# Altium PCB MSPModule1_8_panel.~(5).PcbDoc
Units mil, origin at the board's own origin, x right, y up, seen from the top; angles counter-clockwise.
Board outline 5760 x 6000 mil, 2 copper layers (Top Layer, Bottom Layer); 0 components, 0 nets, 0 pads, 0 vias.
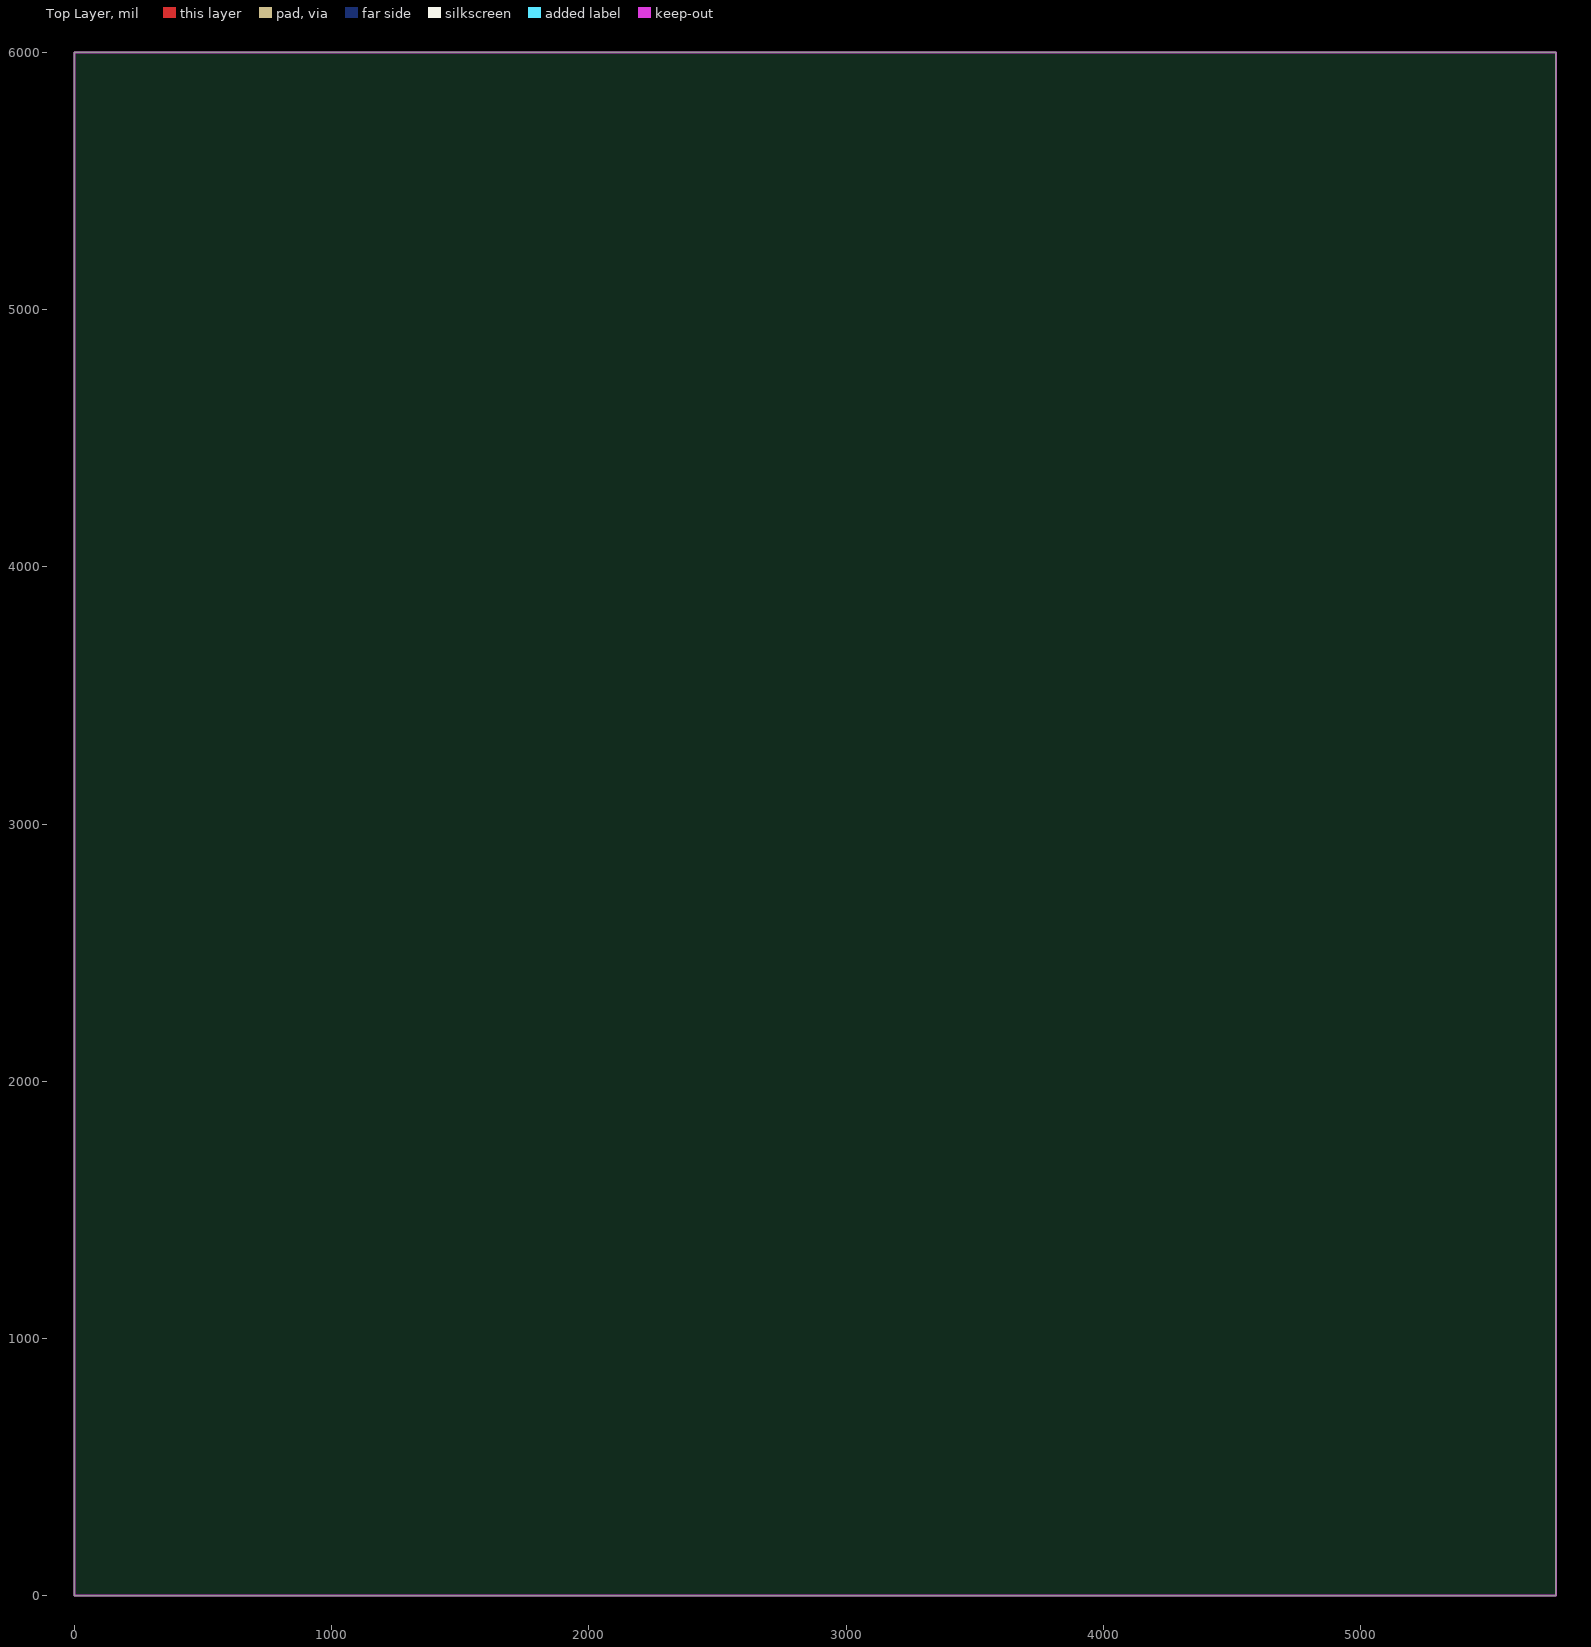
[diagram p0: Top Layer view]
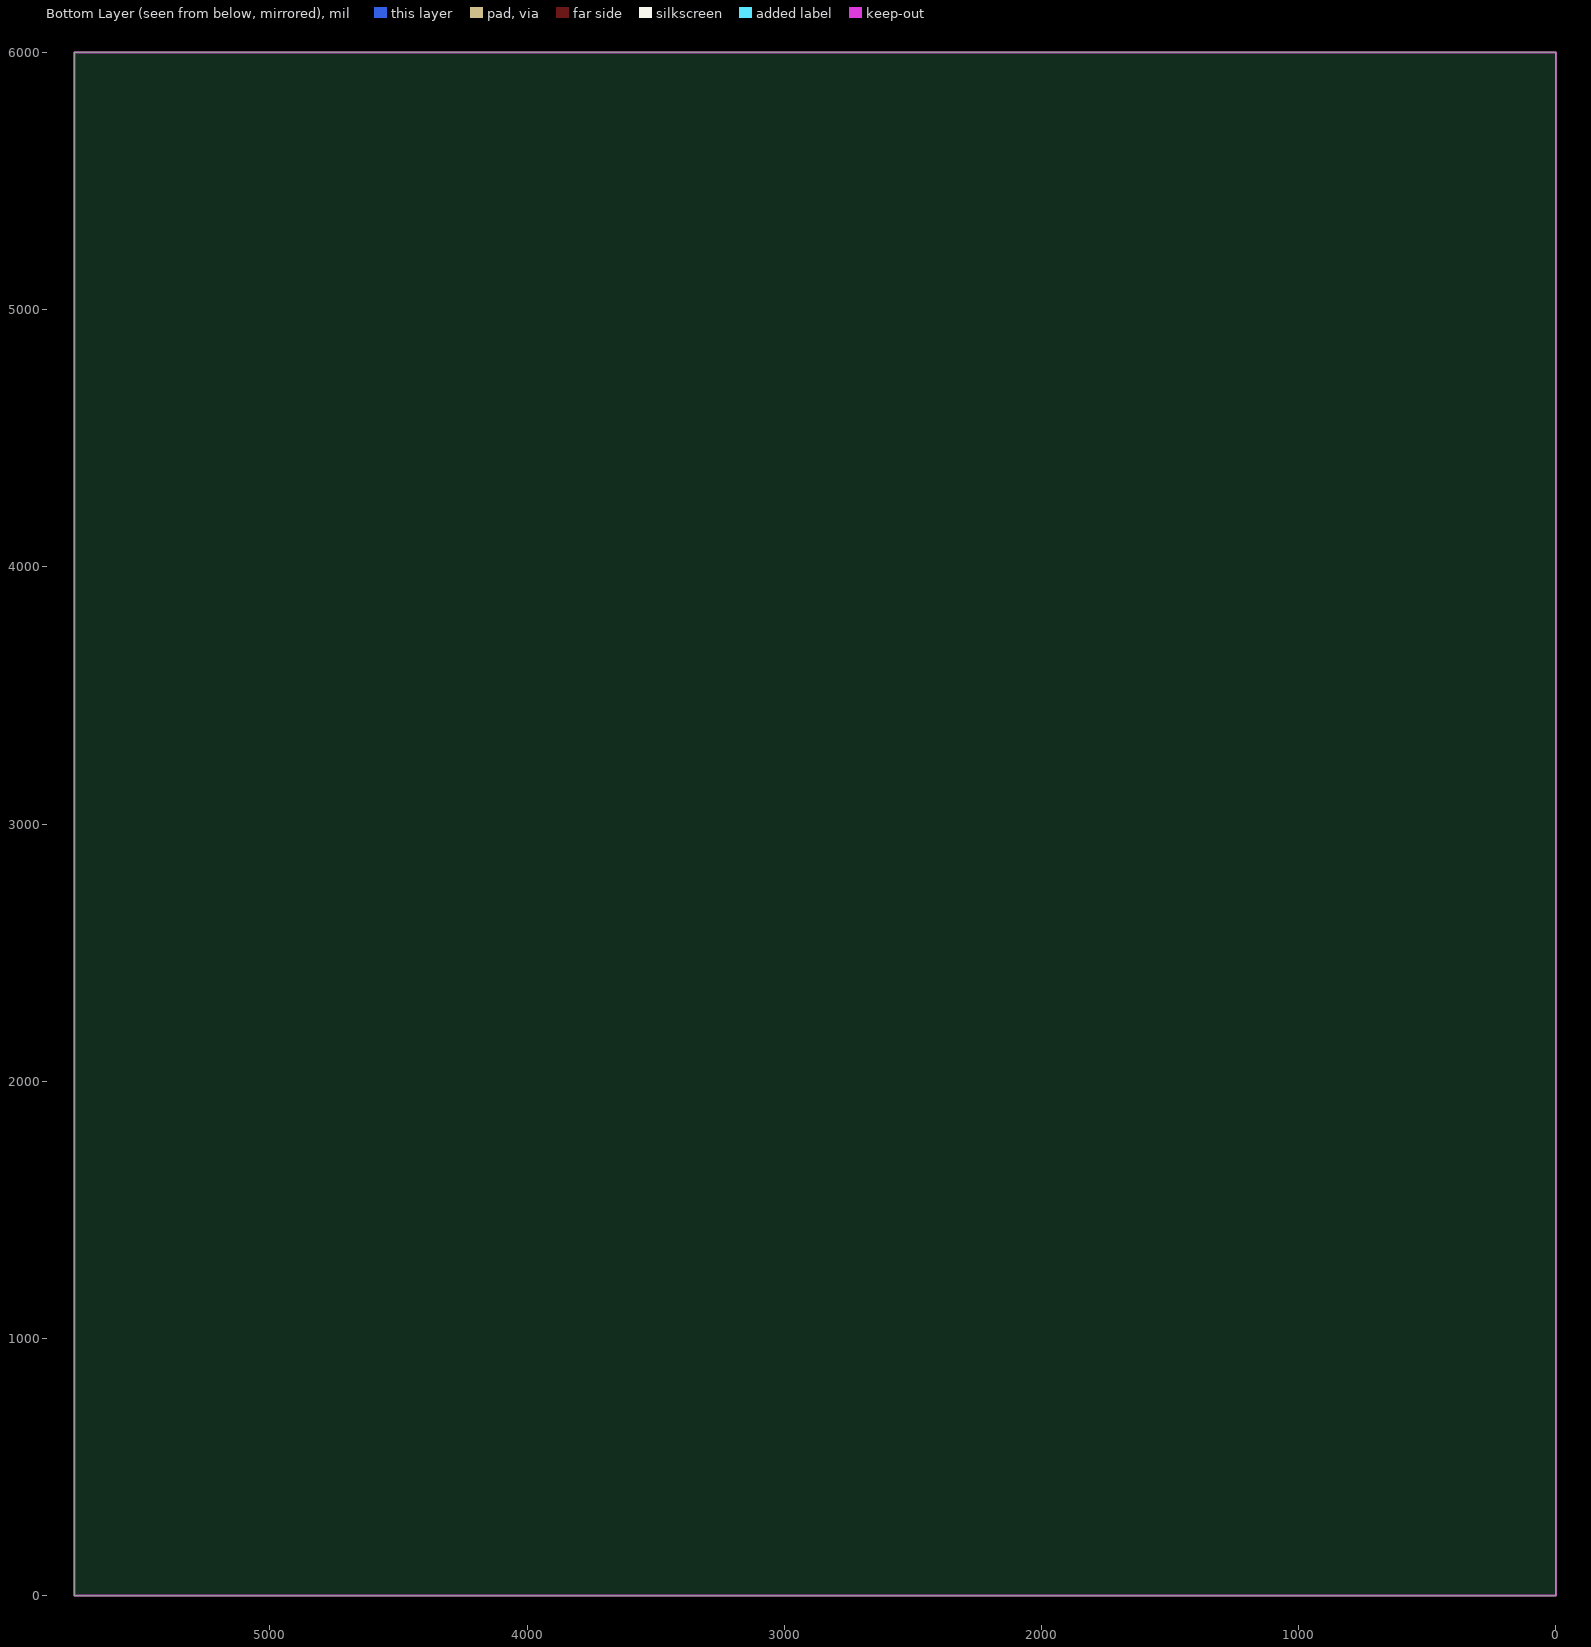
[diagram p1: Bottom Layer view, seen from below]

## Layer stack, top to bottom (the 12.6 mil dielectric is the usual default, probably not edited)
Top Solder: solder mask 0.4, Solder Resist, Dk 3.5
Top Layer: signal copper 1.4
Dielectric 1: dielectric 12.6, FR-4, Dk 4.8
Bottom Layer: signal copper 1.4
Bottom Solder: solder mask 0.4, Solder Resist, Dk 3.5

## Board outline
0,0 0,6000 5760,6000 5760,0

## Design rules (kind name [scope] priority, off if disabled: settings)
Clearance [All] p1: gap=10 ignorepadtopadclearanceinfootprint=FALSE except(0: Arc-Hole Track-Hole SMDPad-Hole THPad-Hole Via-Hole Fill-Hole Poly-Hole Region-Hole Text-Hole)
PolygonConnect [All] p1: connectstyle=Relief reliefconductorwidth=10 reliefentries=4 polygonreliefangle="90 Angle" airgapwidth=10
RoutingVias [All] p1: holewidth=28 width=50 viastyle="Through Hole" minholewidth=28 minwidth=50 maxholewidth=28 maxwidth=50
SolderMaskExpansion [All] p1: expansion=4
Width [All] p1: maxlimit=10 minlimit=10 preferedwidth=10
30 further rules are at their usual default settings.

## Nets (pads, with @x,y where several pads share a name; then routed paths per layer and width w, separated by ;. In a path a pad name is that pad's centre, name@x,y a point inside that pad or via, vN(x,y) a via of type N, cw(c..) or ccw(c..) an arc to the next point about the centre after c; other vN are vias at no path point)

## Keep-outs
Keep-Out Layer:
  the board outline again, w7.87

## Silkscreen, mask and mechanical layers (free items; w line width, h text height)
V-Cut:
  lines w7.87: 0,2000 5760,2000 ; 0,4000 5760,4000 ; 1440,0 1440,6000 ; 2880,0 2880,6000 ; 4320,0 4320,6000

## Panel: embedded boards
"MSPModule1_8.PcbDoc" at 5760,0, 4 rows x 3 columns, spacing 1440 x 2000, rotation 90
